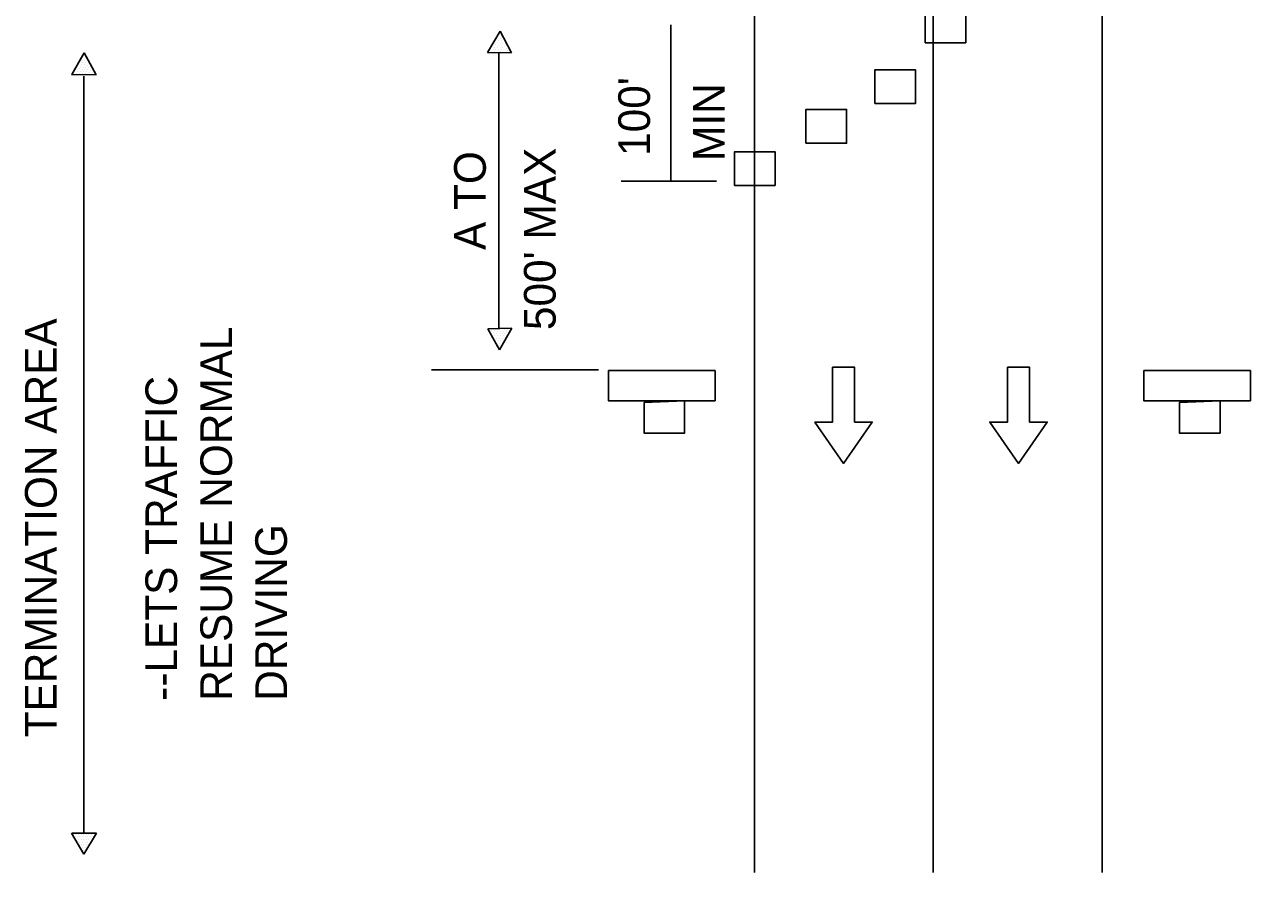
# Model space of a CAD drawing. Extents: x 610.92 to 617.75, y 610.91 to 620.34.
# Drawn here: x 614.427 to 616.748, y 613.32 to 614.926 of the extents above; entities that cross this region are included whole.
import ezdxf

# ---------------------------------------------------------------- set-up
doc = ezdxf.new("R2010")
doc.units = 0
for name, color, linetype in [('DETL-DIMS', 7, 'Continuous'), ('DETL-LINE', 7, 'Continuous'), ('DETL-NOTE', 7, 'Continuous'), ('USER-BORD', 7, 'Continuous')]:
    doc.layers.add(name, color=color, linetype=linetype)

# ---------------------------------------------------------------- blocks, each defined once
blk = doc.blocks.new('SIGN15')
at = {"layer": 'USER-BORD'}
for points in [[(-0.0013, 0.0018), (0.0011, 0.0019), (0.0011, 0.0037), (-0.0013, 0.0037)], [(-0.0031, 0.0018), (-0.0031, 0), (0.0032, 0), (0.0032, 0.0018)]]:
    blk.add_lwpolyline(points, close=True, dxfattribs=at)
blk = doc.blocks.new('DIR4')
at = {"layer": 'USER-BORD'}
for p, q in [((0, 0.0001), (-0.0034, -0.0048)), ((0, 0.0001), (0.0034, -0.0048)), ((-0.0034, -0.0048), (-0.0013, -0.0048)), ((-0.0013, -0.0113), (-0.0013, -0.0048)), ((0.0034, -0.0048), (0.0013, -0.0048)), ((0.0013, -0.0113), (0.0013, -0.0048)), ((-0.0001, -0.0113), (-0.0013, -0.0113)), ((-0.0001, -0.0113), (0.0001, -0.0113)), ((0.0001, -0.0113), (0.0013, -0.0113))]:
    blk.add_line(p, q, dxfattribs=at)

msp = doc.modelspace()

# ---------------------------------------------------------------- linework, layer by layer
at = {"layer": 'DETL-DIMS'}
for p, q in [((615.6502, 614.9252), (615.6502, 614.6292)), ((615.303, 614.8732), (615.327, 614.9132)), ((615.303, 614.8732), (615.327, 614.9132)), ((615.3206, 614.9004), (615.3206, 614.9004)), ((615.3206, 614.9004), (615.3206, 614.9004)), ((615.323, 614.9052), (615.323, 614.9052)), ((615.323, 614.9052), (615.323, 614.9052)), ((615.3254, 614.9092), (615.3254, 614.9092)), ((615.3254, 614.9092), (615.3254, 614.9092)), ((615.327, 614.9132), (615.3486, 614.8724)), ((615.327, 614.9132), (615.3486, 614.8724)), ((615.327, 614.9004), (615.327, 614.9004)), ((615.327, 614.9004), (615.327, 614.9004)), ((615.3294, 614.9044), (615.3294, 614.9044)), ((615.3294, 614.9044), (615.3294, 614.9044)), ((615.3326, 614.9004), (615.3326, 614.9004)), ((615.3326, 614.9004), (615.3326, 614.9004)), ((615.3054, 614.8748), (615.3054, 614.8748)), ((615.3054, 614.8748), (615.3054, 614.8748)), ((615.3078, 614.8788), (615.3078, 614.8788)), ((615.3078, 614.8788), (615.3078, 614.8788)), ((615.3102, 614.8836), (615.3102, 614.8836)), ((615.3102, 614.8836), (615.3102, 614.8836)), ((615.3134, 614.8884), (615.3134, 614.8884)), ((615.3134, 614.8884), (615.3134, 614.8884)), ((615.3142, 614.878), (615.3142, 614.878)), ((615.3142, 614.878), (615.3142, 614.878)), ((615.3158, 614.8924), (615.3158, 614.8924)), ((615.3158, 614.8924), (615.3158, 614.8924)), ((615.3166, 614.8828), (615.3166, 614.8828)), ((615.3166, 614.8828), (615.3166, 614.8828)), ((615.3182, 614.8964), (615.3182, 614.8964)), ((615.3182, 614.8964), (615.3182, 614.8964)), ((615.319, 614.8876), (615.319, 614.8876)), ((615.319, 614.8876), (615.319, 614.8876)), ((615.319, 614.878), (615.319, 614.878)), ((615.319, 614.878), (615.319, 614.878)), ((615.3214, 614.8916), (615.3214, 614.8916)), ((615.3214, 614.8916), (615.3214, 614.8916)), ((615.3222, 614.8828), (615.3222, 614.8828)), ((615.3222, 614.8828), (615.3222, 614.8828)), ((615.3238, 614.8956), (615.3238, 614.8956)), ((615.3238, 614.8956), (615.3238, 614.8956)), ((615.3246, 614.8868), (615.3246, 614.8868)), ((615.3246, 614.8868), (615.3246, 614.8868)), ((615.3246, 614.878), (615.3246, 614.878)), ((615.3246, 614.878), (615.3246, 614.878)), ((615.327, 614.8908), (615.327, 614.8908)), ((615.327, 614.8908), (615.327, 614.8908)), ((615.3278, 614.8828), (615.3278, 614.8828)), ((615.3278, 614.8828), (615.3278, 614.8828)), ((615.3294, 614.8948), (615.3294, 614.8948)), ((615.3294, 614.8948), (615.3294, 614.8948)), ((615.3302, 614.8868), (615.3302, 614.8868)), ((615.3302, 614.8868), (615.3302, 614.8868)), ((615.3302, 614.878), (615.3302, 614.878)), ((615.3302, 614.878), (615.3302, 614.878)), ((615.3326, 614.8908), (615.3326, 614.8908)), ((615.3326, 614.8908), (615.3326, 614.8908)), ((615.3326, 614.882), (615.3326, 614.882)), ((615.3326, 614.882), (615.3326, 614.882)), ((615.335, 614.8956), (615.335, 614.8956)), ((615.335, 614.8956), (615.335, 614.8956)), ((615.335, 614.886), (615.335, 614.886)), ((615.335, 614.886), (615.335, 614.886)), ((615.3366, 614.8772), (615.3366, 614.8772)), ((615.3366, 614.8772), (615.3366, 614.8772)), ((615.3374, 614.89), (615.3374, 614.89)), ((615.3374, 614.89), (615.3374, 614.89)), ((615.339, 614.8812), (615.339, 614.8812)), ((615.339, 614.8812), (615.339, 614.8812)), ((615.3414, 614.8852), (615.3414, 614.8852)), ((615.3414, 614.8852), (615.3414, 614.8852)), ((615.3414, 614.8764), (615.3414, 614.8764)), ((615.3414, 614.8764), (615.3414, 614.8764)), ((614.5166, 614.8316), (614.5398, 614.8724)), ((614.531, 614.8548), (614.531, 614.8548)), ((614.5342, 614.8588), (614.5342, 614.8588)), ((614.5366, 614.8636), (614.5366, 614.8636)), ((614.5374, 614.854), (614.5374, 614.854)), ((614.539, 614.8684), (614.539, 614.8684)), ((614.5398, 614.8724), (614.5622, 614.8308)), ((614.5406, 614.8588), (614.5406, 614.8588)), ((614.543, 614.8628), (614.543, 614.8628)), ((614.543, 614.854), (614.543, 614.854)), ((614.5454, 614.8588), (614.5454, 614.8588)), ((614.5486, 614.854), (614.5486, 614.854)), ((615.303, 614.8732), (615.303, 614.8732)), ((615.3486, 614.8724), (615.303, 614.8732)), ((615.3486, 614.8724), (615.303, 614.8732)), ((615.303, 614.8732), (615.303, 614.8732)), ((615.3118, 614.874), (615.3118, 614.874)), ((615.3118, 614.874), (615.3118, 614.874)), ((615.3166, 614.874), (615.3166, 614.874)), ((615.3166, 614.874), (615.3166, 614.874)), ((615.3222, 614.8732), (615.3222, 614.8732)), ((615.3222, 614.8732), (615.3222, 614.8732)), ((615.3246, 614.3508), (615.3246, 614.8724)), ((615.3278, 614.874), (615.3278, 614.874)), ((615.3278, 614.874), (615.3278, 614.874)), ((615.3342, 614.8732), (615.3342, 614.8732)), ((615.3342, 614.8732), (615.3342, 614.8732)), ((614.5158, 614.8316), (614.5158, 614.8316)), ((614.5622, 614.8308), (614.5158, 614.8316)), ((614.519, 614.834), (614.519, 614.834)), ((614.5214, 614.838), (614.5214, 614.838)), ((614.5238, 614.842), (614.5238, 614.842)), ((614.5246, 614.8332), (614.5246, 614.8332)), ((614.5262, 614.8468), (614.5262, 614.8468)), ((614.527, 614.8372), (614.527, 614.8372)), ((614.5286, 614.8508), (614.5286, 614.8508)), ((614.5302, 614.842), (614.5302, 614.842)), ((614.5302, 614.8324), (614.5302, 614.8324)), ((614.5326, 614.846), (614.5326, 614.846)), ((614.5326, 614.8364), (614.5326, 614.8364)), ((614.535, 614.85), (614.535, 614.85)), ((614.5358, 614.8412), (614.5358, 614.8412)), ((614.5358, 614.8324), (614.5358, 614.8324)), ((614.5382, 614.8452), (614.5382, 614.8452)), ((614.5382, 614.8372), (614.5382, 614.8372)), ((614.539, 613.3956), (614.539, 614.8284)), ((614.5406, 614.85), (614.5406, 614.85)), ((614.5406, 614.8412), (614.5406, 614.8412)), ((614.5414, 614.8324), (614.5414, 614.8324)), ((614.543, 614.8452), (614.543, 614.8452)), ((614.5438, 614.8364), (614.5438, 614.8364)), ((614.5454, 614.8492), (614.5454, 614.8492)), ((614.5462, 614.8404), (614.5462, 614.8404)), ((614.547, 614.8316), (614.547, 614.8316)), ((614.5486, 614.8444), (614.5486, 614.8444)), ((614.5494, 614.8356), (614.5494, 614.8356)), ((614.551, 614.8492), (614.551, 614.8492)), ((614.5518, 614.8396), (614.5518, 614.8396)), ((614.555, 614.8436), (614.555, 614.8436)), ((614.555, 614.8356), (614.555, 614.8356)), ((615.3246, 614.3508), (615.3246, 614.7748)), ((615.5566, 614.6292), (615.7366, 614.6292)), ((615.3038, 614.35), (615.3494, 614.3508)), ((615.3038, 614.35), (615.3494, 614.3508)), ((615.3262, 614.31), (615.3038, 614.35)), ((615.3262, 614.31), (615.3038, 614.35)), ((615.311, 614.346), (615.311, 614.346)), ((615.311, 614.346), (615.311, 614.346)), ((615.3142, 614.342), (615.3142, 614.342)), ((615.3142, 614.342), (615.3142, 614.342)), ((615.3158, 614.346), (615.3158, 614.346)), ((615.3158, 614.346), (615.3158, 614.346)), ((615.3182, 614.35), (615.3182, 614.35)), ((615.3182, 614.35), (615.3182, 614.35)), ((615.3198, 614.3412), (615.3198, 614.3412)), ((615.3198, 614.3412), (615.3198, 614.3412)), ((615.3222, 614.3452), (615.3222, 614.3452)), ((615.3222, 614.3452), (615.3222, 614.3452)), ((615.3246, 614.3492), (615.3246, 614.3492)), ((615.3246, 614.3492), (615.3246, 614.3492)), ((615.3494, 614.3508), (615.3262, 614.31)), ((615.3494, 614.3508), (615.3262, 614.31)), ((615.3278, 614.3452), (615.3278, 614.3452)), ((615.3278, 614.3452), (615.3278, 614.3452)), ((615.3302, 614.35), (615.3302, 614.35)), ((615.3302, 614.35), (615.3302, 614.35)), ((615.3334, 614.3452), (615.3334, 614.3452)), ((615.3334, 614.3452), (615.3334, 614.3452)), ((615.3358, 614.3492), (615.3358, 614.3492)), ((615.3358, 614.3492), (615.3358, 614.3492)), ((615.339, 614.3452), (615.339, 614.3452)), ((615.339, 614.3452), (615.339, 614.3452)), ((615.3414, 614.3492), (615.3414, 614.3492)), ((615.3414, 614.3492), (615.3414, 614.3492)), ((615.3446, 614.3444), (615.3446, 614.3444)), ((615.3446, 614.3444), (615.3446, 614.3444)), ((615.347, 614.3484), (615.347, 614.3484)), ((615.347, 614.3484), (615.347, 614.3484)), ((615.3494, 614.3508), (615.3494, 614.3508)), ((615.3494, 614.3508), (615.3494, 614.3508)), ((615.3118, 614.3372), (615.3118, 614.3372)), ((615.3118, 614.3372), (615.3118, 614.3372)), ((615.315, 614.3324), (615.315, 614.3324)), ((615.315, 614.3324), (615.315, 614.3324)), ((615.3174, 614.3372), (615.3174, 614.3372)), ((615.3174, 614.3372), (615.3174, 614.3372)), ((615.3174, 614.3276), (615.3174, 614.3276)), ((615.3174, 614.3276), (615.3174, 614.3276)), ((615.3206, 614.3324), (615.3206, 614.3324)), ((615.3206, 614.3324), (615.3206, 614.3324)), ((615.3206, 614.3228), (615.3206, 614.3228)), ((615.3206, 614.3228), (615.3206, 614.3228)), ((615.323, 614.3364), (615.323, 614.3364)), ((615.323, 614.3364), (615.323, 614.3364)), ((615.3238, 614.3276), (615.3238, 614.3276)), ((615.3238, 614.3276), (615.3238, 614.3276)), ((615.3238, 614.3188), (615.3238, 614.3188)), ((615.3238, 614.3188), (615.3238, 614.3188)), ((615.3254, 614.3404), (615.3254, 614.3404)), ((615.3254, 614.3404), (615.3254, 614.3404)), ((615.3262, 614.3324), (615.3262, 614.3324)), ((615.3262, 614.3324), (615.3262, 614.3324)), ((615.3262, 614.3228), (615.3262, 614.3228)), ((615.3262, 614.3228), (615.3262, 614.3228)), ((615.3286, 614.3364), (615.3286, 614.3364)), ((615.3286, 614.3364), (615.3286, 614.3364)), ((615.3286, 614.3276), (615.3286, 614.3276)), ((615.3286, 614.3276), (615.3286, 614.3276)), ((615.3302, 614.318), (615.3302, 614.318)), ((615.3302, 614.318), (615.3302, 614.318)), ((615.331, 614.3404), (615.331, 614.3404)), ((615.331, 614.3404), (615.331, 614.3404)), ((615.331, 614.3316), (615.331, 614.3316)), ((615.331, 614.3316), (615.331, 614.3316)), ((615.3326, 614.3228), (615.3326, 614.3228)), ((615.3326, 614.3228), (615.3326, 614.3228)), ((615.3334, 614.3364), (615.3334, 614.3364)), ((615.3334, 614.3364), (615.3334, 614.3364)), ((615.335, 614.3268), (615.335, 614.3268)), ((615.335, 614.3268), (615.335, 614.3268)), ((615.3358, 614.3404), (615.3358, 614.3404)), ((615.3358, 614.3404), (615.3358, 614.3404)), ((615.3374, 614.3316), (615.3374, 614.3316)), ((615.3374, 614.3316), (615.3374, 614.3316)), ((615.3398, 614.3356), (615.3398, 614.3356)), ((615.3398, 614.3356), (615.3398, 614.3356)), ((615.3422, 614.3404), (615.3422, 614.3404)), ((615.3422, 614.3404), (615.3422, 614.3404)), ((615.3278, 614.314), (615.3278, 614.314)), ((615.3278, 614.314), (615.3278, 614.314)), ((615.1974, 614.2724), (615.5134, 614.2724)), ((614.539, 613.3548), (614.5158, 613.3948)), ((614.5158, 613.3948), (614.5158, 613.3948)), ((614.5166, 613.3948), (614.563, 613.3948)), ((614.519, 613.3932), (614.519, 613.3932)), ((614.5238, 613.3932), (614.5238, 613.3932)), ((614.5286, 613.3932), (614.5286, 613.3932)), ((614.5342, 613.3932), (614.5342, 613.3932)), ((614.563, 613.3948), (614.539, 613.3548)), ((614.539, 613.3932), (614.539, 613.3932)), ((614.5438, 613.3932), (614.5438, 613.3932)), ((614.5486, 613.3932), (614.5486, 613.3932)), ((614.5542, 613.3932), (614.5542, 613.3932)), ((614.559, 613.3932), (614.559, 613.3932)), ((614.5214, 613.3876), (614.5214, 613.3876)), ((614.5238, 613.3828), (614.5238, 613.3828)), ((614.5262, 613.3876), (614.5262, 613.3876)), ((614.5262, 613.378), (614.5262, 613.378)), ((614.5286, 613.3828), (614.5286, 613.3828)), ((614.5294, 613.3732), (614.5294, 613.3732)), ((614.5318, 613.3876), (614.5318, 613.3876)), ((614.5318, 613.378), (614.5318, 613.378)), ((614.5318, 613.3676), (614.5318, 613.3676)), ((614.5342, 613.3828), (614.5342, 613.3828)), ((614.5342, 613.3732), (614.5342, 613.3732)), ((614.5366, 613.3876), (614.5366, 613.3876)), ((614.5366, 613.378), (614.5366, 613.378)), ((614.5366, 613.3676), (614.5366, 613.3676)), ((614.539, 613.3828), (614.539, 613.3828)), ((614.539, 613.3732), (614.539, 613.3732)), ((614.5414, 613.3876), (614.5414, 613.3876)), ((614.5414, 613.378), (614.5414, 613.378)), ((614.5414, 613.3676), (614.5414, 613.3676)), ((614.5438, 613.3828), (614.5438, 613.3828)), ((614.5438, 613.3732), (614.5438, 613.3732)), ((614.5462, 613.3876), (614.5462, 613.3876)), ((614.5462, 613.378), (614.5462, 613.378)), ((614.5462, 613.3676), (614.5462, 613.3676)), ((614.5486, 613.3828), (614.5486, 613.3828)), ((614.5486, 613.3732), (614.5486, 613.3732)), ((614.5518, 613.3876), (614.5518, 613.3876)), ((614.5518, 613.378), (614.5518, 613.378)), ((614.5542, 613.3828), (614.5542, 613.3828)), ((614.5566, 613.3876), (614.5566, 613.3876)), ((614.539, 613.3628), (614.539, 613.3628))]:
    msp.add_line(p, q, dxfattribs=at)
at = {"layer": 'DETL-LINE'}
for p, q in [((615.8086, 613.3204), (615.8086, 620.3372)), ((616.147, 613.3204), (616.147, 620.3316)), ((616.467, 613.3204), (616.467, 620.3372))]:
    msp.add_line(p, q, dxfattribs=at)
for points in [[(616.1318, 614.8916), (616.1318, 614.9556), (616.2086, 614.9556), (616.2086, 614.8916)], [(616.1318, 614.8916), (616.1318, 614.9556), (616.2086, 614.9556), (616.2086, 614.8916)], [(616.0366, 614.7764), (616.0366, 614.8404), (616.1134, 614.8404), (616.1134, 614.7764)], [(615.9062, 614.7012), (615.9062, 614.7652), (615.983, 614.7652), (615.983, 614.7012)], [(615.771, 614.6212), (615.771, 614.6852), (615.8478, 614.6852), (615.8478, 614.6212)], [(615.9566, 614.2772), (615.9982, 614.2772), (615.9982, 614.1732), (616.0318, 614.1732), (615.9774, 614.0948), (615.923, 614.1732), (615.9566, 614.1732)], [(616.2878, 614.2772), (616.3294, 614.2772), (616.3294, 614.1732), (616.363, 614.1732), (616.3086, 614.0948), (616.2542, 614.1732), (616.2878, 614.1732)]]:
    msp.add_lwpolyline(points, close=True, dxfattribs=at)
for points in [[(616.147, 614.4604), (616.147, 614.5804)], [(616.147, 613.9804), (616.147, 614.1004)], [(616.147, 613.5004), (616.147, 613.6204)]]:
    msp.add_lwpolyline(points, dxfattribs=at)

# ---------------------------------------------------------------- block references
at = {"layer": 'DETL-LINE', "rotation": 180}
for name, p, xscale, yscale in [('DIR4', (615.9773, 614.0964), 16, 16), ('DIR4', (615.9773, 614.0964), 16, 16), ('DIR4', (616.3085, 614.0964), 16, 16), ('SIGN15', (615.6349, 614.2708), 32, 32), ('SIGN15', (616.6485, 614.2708), 32, 32)]:
    msp.add_blockref(name, p, dxfattribs=dict(at, xscale=xscale, yscale=yscale))

# ---------------------------------------------------------------- texts
at = {"layer": 'DETL-NOTE'}
for s, p in [("100'", (615.6109, 614.6772)), ('MIN', (615.7525, 614.6676)), ("500' MAX", (615.4323, 614.3474)), ('A TO', (615.3001, 614.499)), ('TERMINATION AREA', (614.4877, 613.5762)), ('RESUME NORMAL', (614.8197, 613.6455)), ('--LETS TRAFFIC', (614.7157, 613.6455)), ('DRIVING', (614.9237, 613.6455))]:
    msp.add_text(s, height=0.06, rotation=90, dxfattribs=at).set_placement(p)

doc.saveas('drawing.dxf')
